Omron CX-Programmer project 新規ﾌﾟﾛｼﾞｪｸﾄ (CX-Programmer 9.70)

# PLC 湯沸しPLC: CJ2M CPU34
I/O table (CPU CJ2M-CPU34): rack 0 slot 0 CJ1W-ID231; rack 0 slot 1 CJ1W-OD231; rack 0 slot 2 CJ1W-AD041-V1; rack 0 slot 11 CJ2M-EIP21

## Global symbols (name address type ; comment)
0.00 BOOL  ; 自動選択
0.01 BOOL  ; 手動選択
0.02 BOOL  ; 運転開始PB
0.03 BOOL  ; 運転停止PB
0.08 BOOL  ; 手動給水ﾊﾞﾙﾌﾞ開
0.09 BOOL  ; 手動給水ﾎﾟﾝﾌﾟ運転
0.10 BOOL  ; 手動排水ﾊﾞﾙﾌﾞ開
0.11 BOOL  ; 手動排水ﾊﾞﾙﾌﾞ閉
0.12 BOOL  ; 手動排水ﾎﾟﾝﾌﾟ運転
0.13 BOOL  ; 手動過熱
1.00 BOOL  ; 給水ﾊﾞﾙﾌﾞ開確認
1.01 BOOL  ; 給水ﾊﾞﾙﾌﾞ閉確認
1.02 BOOL  ; 排水ﾊﾞﾙﾌﾞ開確認
1.03 BOOL  ; 排水ﾊﾞﾙﾌﾞ閉確認
1.08 BOOL  ; 下限
1.09 BOOL  ; 上限
1.10 BOOL  ; 上上限
2000 CHANNEL  ; ﾋﾟｰｸﾎｰﾙﾄﾞ機能
2001 CHANNEL  ; 水温(BIN)
2002 CHANNEL  ; CH2値
2003 CHANNEL  ; CH3値
2004 CHANNEL  ; CH4値
2009 CHANNEL  ; ADｱﾗｰﾑ
2.00 BOOL  ; 自動運転中表示
2.01 BOOL  ; 停止中表示
3000 CHANNEL  ; 演算ﾜｰｸL
3001 CHANNEL  ; 演算ﾜｰｸH
3002 CHANNEL  ; 演算ﾜｰｸL
3003 CHANNEL  ; 演算ﾜｰｸH
3004 CHANNEL  ; 水温(℃)
3.00 BOOL  ; 給水ﾎﾟﾝﾌﾟ
3.01 BOOL  ; 排水ﾎﾟﾝﾌﾟ
3.02 BOOL  ; 給水ﾊﾞﾙﾌﾞ　開
3.03 BOOL  ; 排水ﾊﾞﾙﾌﾞ　開
3.04 BOOL  ; 排水ﾊﾞﾙﾌﾞ 閉
3.15 BOOL  ; 加熱ﾋｰﾀｰ
T0000 BOOL  ; 下限確認
T0001 BOOL  ; 上限確認
T0002 BOOL  ; 上上限確認
T0010 BOOL  ; 加熱遅延
T0011 BOOL  ; 排水遅延
T0012 BOOL  ; 次ｻｲｸﾙ遅延
W0.00 BOOL  ; 自動運転
W0.01 BOOL  ; 自動運転中
W0.03 BOOL  ; 水温　90℃到達
W0.04 BOOL  ; 排水
W0.05 BOOL  ; 排水ﾎﾟﾝﾌﾟ運転
W0.06 BOOL  ; 排水終了
W0.07 BOOL  ; 1ｻｲｸﾙ終了
W0.08 BOOL  ; 次ｻｲｸﾙ準備
W10.00 BOOL  ; 給水ﾊﾞﾙﾌﾞ開
W10.01 BOOL  ; 給水ﾎﾟﾝﾌﾟ運転
W10.02 BOOL  ; 加熱
W3.00 BOOL  ; 手動
W3.01 BOOL  ; 排水ﾊﾞﾙﾌﾞ開
W6.00 BOOL  ; 自動運転中

## Program 新規ﾌﾟﾛｸﾞﾗﾑ1 (cyclic task 0)
Local symbols
上上限 BOOL

### Section 自動

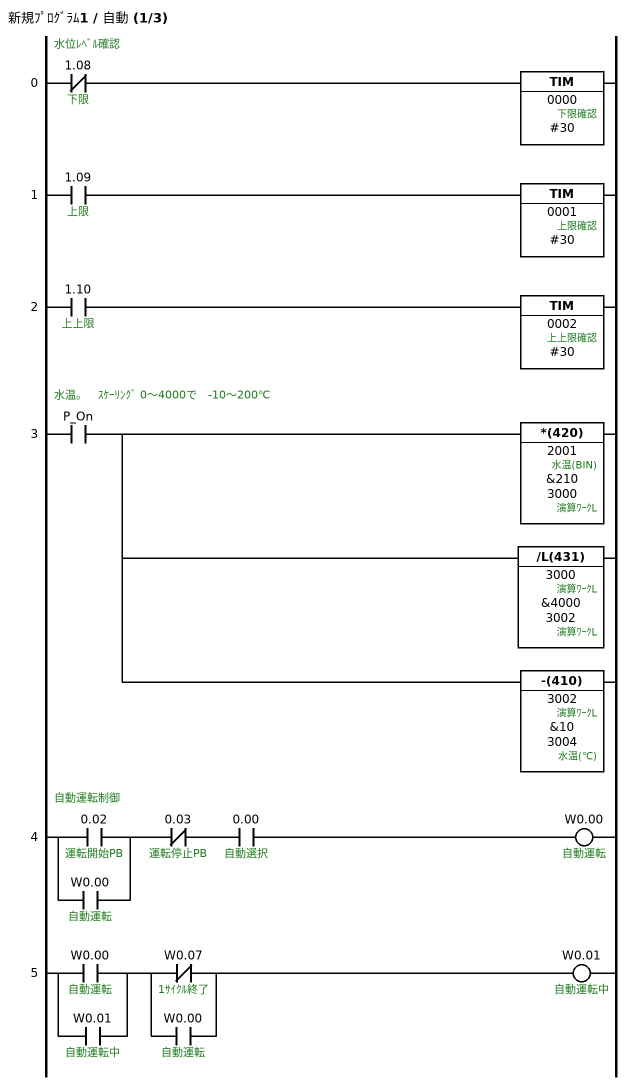
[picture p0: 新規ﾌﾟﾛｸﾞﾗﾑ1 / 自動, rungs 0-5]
; rung 0: 水位ﾚﾍﾞﾙ確認
LDNOT 1.08  ; 下限
TIM 0000 #30  ; 下限確認
; rung 1
LD 1.09  ; 上限
TIM 0001 #30  ; 上限確認
; rung 2
LD 1.10  ; 上上限
TIM 0002 #30  ; 上上限確認
; rung 3: 水温。　ｽｹｰﾘﾝｸﾞ 0～4000で　-10～200℃
LD P_On
*(420) 2001 &210 3000  ; 水温(BIN), 演算ﾜｰｸL
/L(431) 3000 &4000 3002  ; 演算ﾜｰｸL
-(410) 3002 &10 3004  ; 演算ﾜｰｸL, 水温(℃)
; rung 4: 自動運転制御
LD 0.02  ; 運転開始PB
OR W0.00  ; 自動運転
ANDNOT 0.03  ; 運転停止PB
AND 0.00  ; 自動選択
OUT W0.00  ; 自動運転
; rung 5
LD W0.00  ; 自動運転
OR W0.01  ; 自動運転中
LDNOT W0.07  ; 1ｻｲｸﾙ終了
OR W0.00  ; 自動運転
ANDLD
OUT W0.01  ; 自動運転中

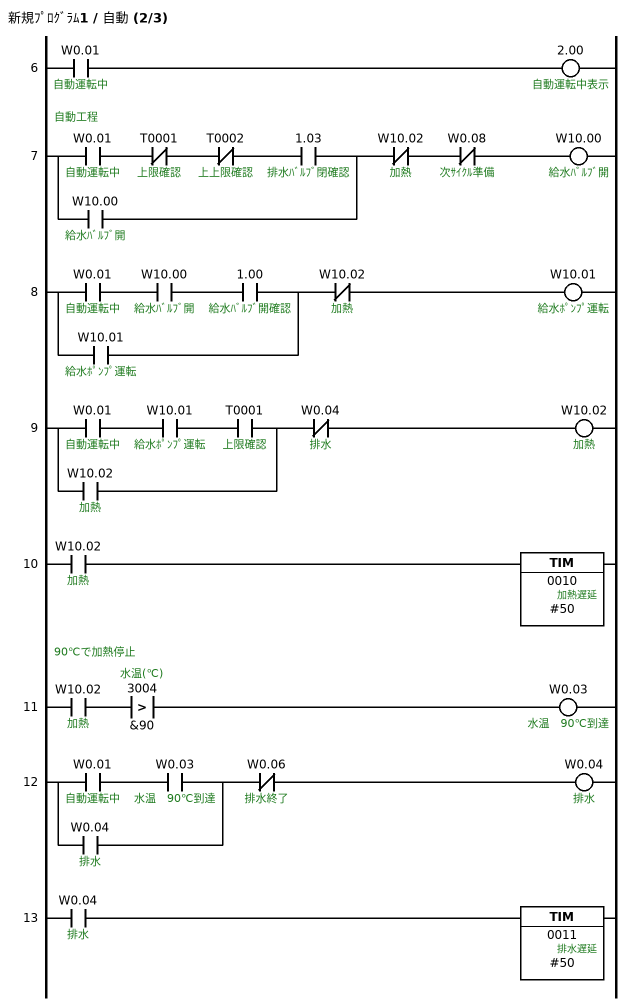
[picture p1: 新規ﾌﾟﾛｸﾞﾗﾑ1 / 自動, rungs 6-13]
; rung 6
LD W0.01  ; 自動運転中
OUT 2.00  ; 自動運転中表示
; rung 7: 自動工程
LD W0.01  ; 自動運転中
ANDNOT T0001  ; 上限確認
ANDNOT T0002  ; 上上限確認
AND 1.03  ; 排水ﾊﾞﾙﾌﾞ閉確認
OR W10.00  ; 給水ﾊﾞﾙﾌﾞ開
ANDNOT W10.02  ; 加熱
ANDNOT W0.08  ; 次ｻｲｸﾙ準備
OUT W10.00  ; 給水ﾊﾞﾙﾌﾞ開
; rung 8
LD W0.01  ; 自動運転中
AND W10.00  ; 給水ﾊﾞﾙﾌﾞ開
AND 1.00  ; 給水ﾊﾞﾙﾌﾞ開確認
OR W10.01  ; 給水ﾎﾟﾝﾌﾟ運転
ANDNOT W10.02  ; 加熱
OUT W10.01  ; 給水ﾎﾟﾝﾌﾟ運転
; rung 9
LD W0.01  ; 自動運転中
AND W10.01  ; 給水ﾎﾟﾝﾌﾟ運転
AND T0001  ; 上限確認
OR W10.02  ; 加熱
ANDNOT W0.04  ; 排水
OUT W10.02  ; 加熱
; rung 10
LD W10.02  ; 加熱
TIM 0010 #50  ; 加熱遅延
; rung 11: 90℃で加熱停止
LD W10.02  ; 加熱
AND>S(322) 3004 &90  ; 水温(℃)
OUT W0.03  ; 水温　90℃到達
; rung 12
LD W0.01  ; 自動運転中
AND W0.03  ; 水温　90℃到達
OR W0.04  ; 排水
ANDNOT W0.06  ; 排水終了
OUT W0.04  ; 排水
; rung 13
LD W0.04  ; 排水
TIM 0011 #50  ; 排水遅延

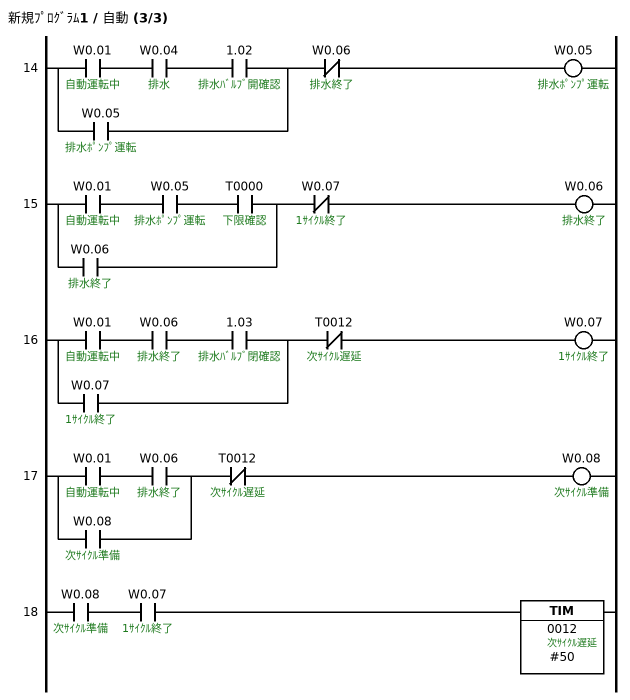
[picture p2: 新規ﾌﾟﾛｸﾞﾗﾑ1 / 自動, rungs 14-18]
; rung 14
LD W0.01  ; 自動運転中
AND W0.04  ; 排水
AND 1.02  ; 排水ﾊﾞﾙﾌﾞ開確認
OR W0.05  ; 排水ﾎﾟﾝﾌﾟ運転
ANDNOT W0.06  ; 排水終了
OUT W0.05  ; 排水ﾎﾟﾝﾌﾟ運転
; rung 15
LD W0.01  ; 自動運転中
AND W0.05  ; 排水ﾎﾟﾝﾌﾟ運転
AND T0000  ; 下限確認
OR W0.06  ; 排水終了
ANDNOT W0.07  ; 1ｻｲｸﾙ終了
OUT W0.06  ; 排水終了
; rung 16
LD W0.01  ; 自動運転中
AND W0.06  ; 排水終了
AND 1.03  ; 排水ﾊﾞﾙﾌﾞ閉確認
OR W0.07  ; 1ｻｲｸﾙ終了
ANDNOT T0012  ; 次ｻｲｸﾙ遅延
OUT W0.07  ; 1ｻｲｸﾙ終了
; rung 17
LD W0.01  ; 自動運転中
AND W0.06  ; 排水終了
OR W0.08  ; 次ｻｲｸﾙ準備
ANDNOT T0012  ; 次ｻｲｸﾙ遅延
OUT W0.08  ; 次ｻｲｸﾙ準備
; rung 18
LD W0.08  ; 次ｻｲｸﾙ準備
AND W0.07  ; 1ｻｲｸﾙ終了
TIM 0012 #50  ; 次ｻｲｸﾙ遅延

### Section 手動

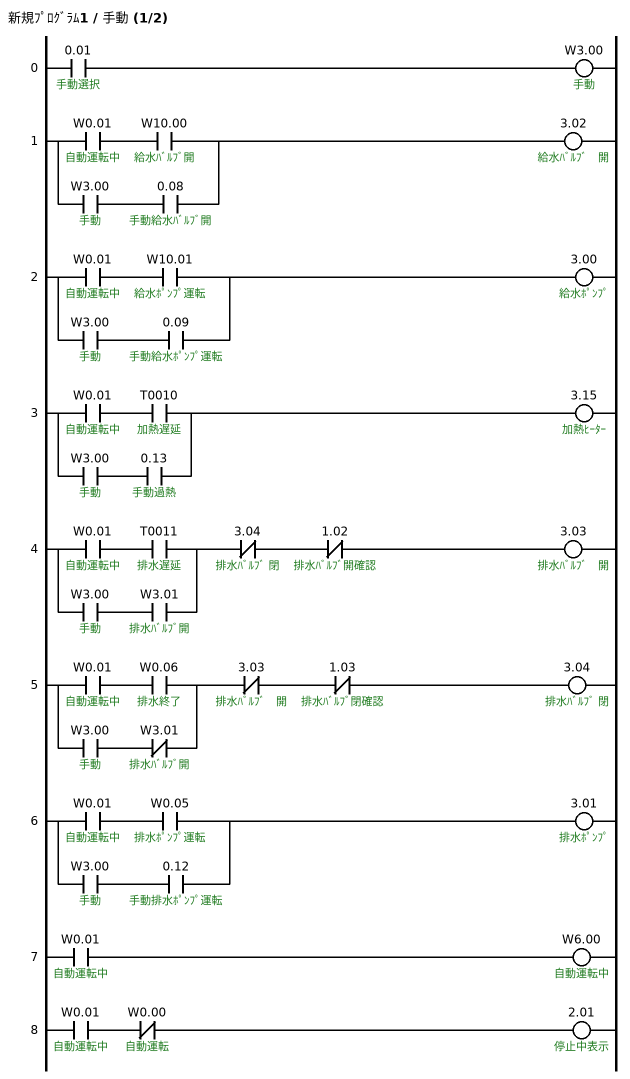
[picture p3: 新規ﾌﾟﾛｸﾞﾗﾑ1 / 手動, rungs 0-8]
; rung 0
LD 0.01  ; 手動選択
OUT W3.00  ; 手動
; rung 1
LD W0.01  ; 自動運転中
AND W10.00  ; 給水ﾊﾞﾙﾌﾞ開
LD W3.00  ; 手動
AND 0.08  ; 手動給水ﾊﾞﾙﾌﾞ開
ORLD
OUT 3.02  ; 給水ﾊﾞﾙﾌﾞ　開
; rung 2
LD W0.01  ; 自動運転中
AND W10.01  ; 給水ﾎﾟﾝﾌﾟ運転
LD W3.00  ; 手動
AND 0.09  ; 手動給水ﾎﾟﾝﾌﾟ運転
ORLD
OUT 3.00  ; 給水ﾎﾟﾝﾌﾟ
; rung 3
LD W0.01  ; 自動運転中
AND T0010  ; 加熱遅延
LD W3.00  ; 手動
AND 0.13  ; 手動過熱
ORLD
OUT 3.15  ; 加熱ﾋｰﾀｰ
; rung 4
LD W0.01  ; 自動運転中
AND T0011  ; 排水遅延
LD W3.00  ; 手動
AND W3.01  ; 排水ﾊﾞﾙﾌﾞ開
ORLD
ANDNOT 3.04  ; 排水ﾊﾞﾙﾌﾞ 閉
ANDNOT 1.02  ; 排水ﾊﾞﾙﾌﾞ開確認
OUT 3.03  ; 排水ﾊﾞﾙﾌﾞ　開
; rung 5
LD W0.01  ; 自動運転中
AND W0.06  ; 排水終了
LD W3.00  ; 手動
ANDNOT W3.01  ; 排水ﾊﾞﾙﾌﾞ開
ORLD
ANDNOT 3.03  ; 排水ﾊﾞﾙﾌﾞ　開
ANDNOT 1.03  ; 排水ﾊﾞﾙﾌﾞ閉確認
OUT 3.04  ; 排水ﾊﾞﾙﾌﾞ 閉
; rung 6
LD W0.01  ; 自動運転中
AND W0.05  ; 排水ﾎﾟﾝﾌﾟ運転
LD W3.00  ; 手動
AND 0.12  ; 手動排水ﾎﾟﾝﾌﾟ運転
ORLD
OUT 3.01  ; 排水ﾎﾟﾝﾌﾟ
; rung 7
LD W0.01  ; 自動運転中
OUT W6.00  ; 自動運転中
; rung 8
LD W0.01  ; 自動運転中
ANDNOT W0.00  ; 自動運転
OUT 2.01  ; 停止中表示

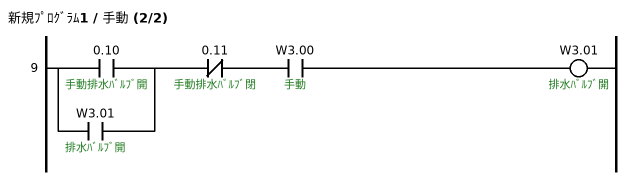
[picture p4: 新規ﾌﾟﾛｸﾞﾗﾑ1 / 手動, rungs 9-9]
; rung 9
LD 0.10  ; 手動排水ﾊﾞﾙﾌﾞ開
OR W3.01  ; 排水ﾊﾞﾙﾌﾞ開
ANDNOT 0.11  ; 手動排水ﾊﾞﾙﾌﾞ閉
AND W3.00  ; 手動
OUT W3.01  ; 排水ﾊﾞﾙﾌﾞ開

### Section END
; rung 0
END(001)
